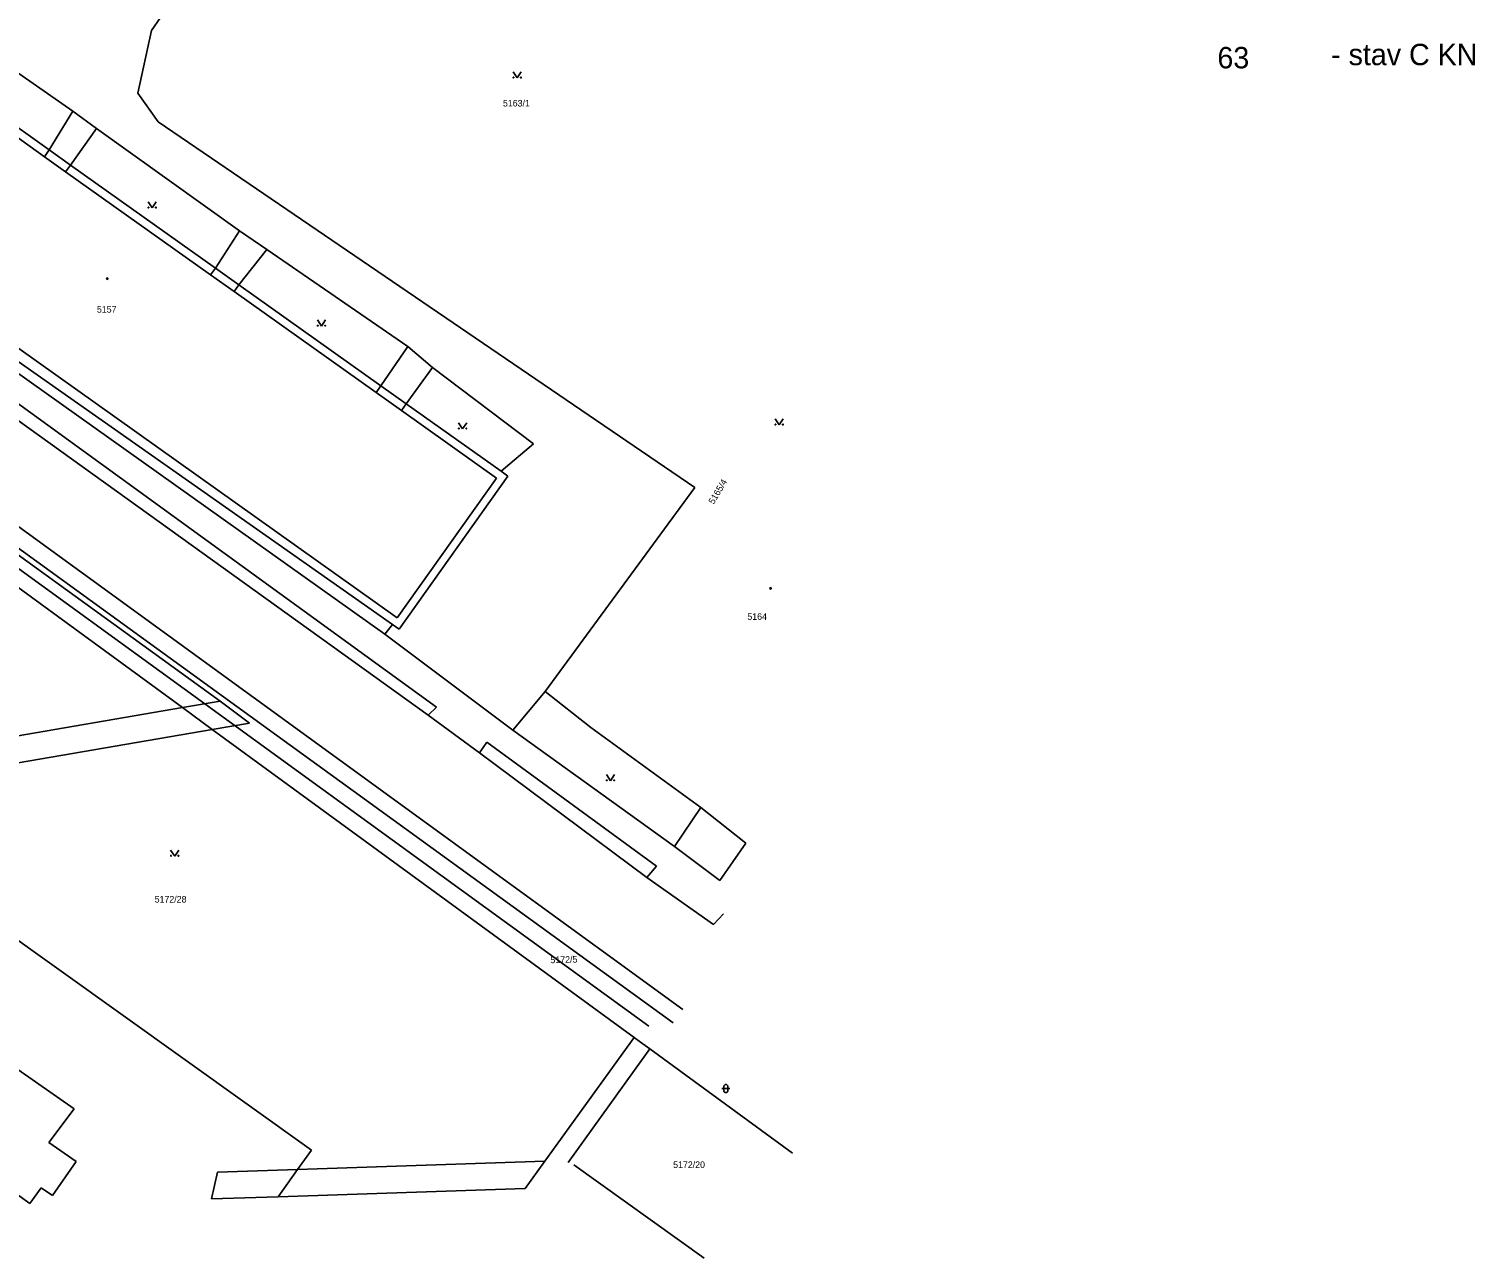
# Model space of a CAD drawing. Extents: x -400488 to -400124, y -1251493 to -1251223.
# Drawn here: x -400248.8 to -400143.3, y -1251492.2 to -1251402.6 of the extents above; entities that cross this region are included whole.
import ezdxf

# ---------------------------------------------------------------- set-up
doc = ezdxf.new("R2010")
doc.units = 0
doc.layers.add('Level 3', color=7, linetype='Continuous')
doc.layers.add('Level 63', color=7, linetype='Continuous')

msp = doc.modelspace()

# ---------------------------------------------------------------- linework, layer by layer
at = {"layer": 'Level 63'}
for p, q in [((-400239.81, -1251402.68), (-400225.97, -1251382.68)), ((-400287.14, -1251402.66), (-400219.04, -1251452.02)), ((-400240.81, -1251407.26), (-400239.81, -1251402.68)), ((-400287.72, -1251403.73), (-400219.65, -1251452.6)), ((-400252.27, -1251403.91), (-400245.56, -1251408.56)), ((-400213.46, -1251405.7), (-400213.16, -1251406.15)), ((-400213.16, -1251406.15), (-400212.86, -1251405.7)), ((-400239.33, -1251409.36), (-400240.81, -1251407.26)), ((-400251.75, -1251408.21), (-400247.28, -1251411.4)), ((-400247.28, -1251411.4), (-400251.75, -1251408.21)), ((-400251.61, -1251409.05), (-400247.63, -1251411.89)), ((-400247.28, -1251411.4), (-400245.56, -1251408.56)), ((-400245.56, -1251408.56), (-400243.84, -1251409.84)), ((-400200.2, -1251436), (-400239.33, -1251409.36)), ((-400245.73, -1251412.5), (-400243.84, -1251409.84)), ((-400243.84, -1251409.84), (-400233.41, -1251417.29)), ((-400247.28, -1251411.4), (-400247.63, -1251411.89)), ((-400247.28, -1251411.4), (-400245.73, -1251412.5)), ((-400245.73, -1251412.5), (-400247.28, -1251411.4)), ((-400287.04, -1251411.61), (-400201.09, -1251474.06)), ((-400247.63, -1251411.89), (-400246.08, -1251412.99)), ((-400245.73, -1251412.5), (-400246.08, -1251412.99)), ((-400245.73, -1251412.5), (-400235.16, -1251420.02)), ((-400235.16, -1251420.02), (-400245.73, -1251412.5)), ((-400286.78, -1251413.41), (-400201.79, -1251475.05)), ((-400246.08, -1251412.99), (-400235.51, -1251420.51)), ((-400203.57, -1251475.28), (-400286.46, -1251415.13)), ((-400240.07, -1251415.18), (-400239.77, -1251415.63)), ((-400239.77, -1251415.63), (-400239.47, -1251415.18)), ((-400235.16, -1251420.02), (-400233.41, -1251417.29)), ((-400233.41, -1251417.29), (-400231.41, -1251418.66)), ((-400233.45, -1251421.23), (-400231.41, -1251418.66)), ((-400231.41, -1251418.66), (-400221.14, -1251425.72)), ((-400258.53, -1251419.46), (-400221.9, -1251445.5)), ((-400258.92, -1251421.03), (-400222.82, -1251446.71)), ((-400222.82, -1251446.71), (-400258.92, -1251421.03)), ((-400222.25, -1251445.99), (-400258.55, -1251420.52)), ((-400258.55, -1251420.52), (-400222.25, -1251445.99)), ((-400235.51, -1251420.51), (-400235.16, -1251420.02)), ((-400233.8, -1251421.72), (-400235.51, -1251420.51)), ((-400235.16, -1251420.02), (-400233.45, -1251421.23)), ((-400233.45, -1251421.23), (-400235.16, -1251420.02)), ((-400233.45, -1251421.23), (-400233.8, -1251421.72)), ((-400223.45, -1251429.08), (-400233.8, -1251421.72)), ((-400233.45, -1251421.23), (-400223.1, -1251428.59)), ((-400223.1, -1251428.59), (-400233.45, -1251421.23)), ((-400227.73, -1251423.79), (-400227.43, -1251424.24)), ((-400227.43, -1251424.24), (-400227.13, -1251423.79)), ((-400223.1, -1251428.59), (-400221.14, -1251425.72)), ((-400221.14, -1251425.72), (-400219.33, -1251427.27)), ((-400221.25, -1251429.91), (-400219.33, -1251427.27)), ((-400219.33, -1251427.27), (-400211.96, -1251432.82)), ((-400223.1, -1251428.59), (-400223.45, -1251429.08)), ((-400221.59, -1251430.4), (-400223.45, -1251429.08)), ((-400223.1, -1251428.59), (-400221.25, -1251429.91)), ((-400221.25, -1251429.91), (-400223.1, -1251428.59)), ((-400221.25, -1251429.91), (-400221.59, -1251430.4)), ((-400214.68, -1251435.32), (-400221.59, -1251430.4)), ((-400221.25, -1251429.91), (-400214.33, -1251434.83)), ((-400214.33, -1251434.83), (-400221.25, -1251429.91)), ((-400217.44, -1251431.29), (-400217.14, -1251431.74)), ((-400217.14, -1251431.74), (-400216.84, -1251431.29)), ((-400194.36, -1251431), (-400194.06, -1251431.45)), ((-400194.06, -1251431.45), (-400193.76, -1251431)), ((-400211.96, -1251432.82), (-400214.33, -1251434.83)), ((-400221.9, -1251445.5), (-400214.68, -1251435.32)), ((-400213.85, -1251435.18), (-400221.76, -1251446.33)), ((-400221.76, -1251446.33), (-400213.85, -1251435.18)), ((-400214.33, -1251434.83), (-400213.85, -1251435.18)), ((-400213.85, -1251435.18), (-400214.33, -1251434.83)), ((-400211.13, -1251450.88), (-400200.2, -1251436)), ((-400200.2, -1251436), (-400211.13, -1251450.88)), ((-400234.81, -1251451.59), (-400250.32, -1251440.37)), ((-400250.32, -1251440.37), (-400234.81, -1251451.59)), ((-400237.56, -1251452.06), (-400251.44, -1251441.92)), ((-400251.44, -1251441.92), (-400237.56, -1251452.06)), ((-400222.25, -1251445.99), (-400222.82, -1251446.71)), ((-400221.76, -1251446.33), (-400222.25, -1251445.99)), ((-400222.25, -1251445.99), (-400221.76, -1251446.33)), ((-400222.82, -1251446.71), (-400213.47, -1251453.7)), ((-400213.47, -1251453.7), (-400222.82, -1251446.71)), ((-400237.56, -1251452.06), (-400234.81, -1251451.59)), ((-400232.67, -1251453.18), (-400234.81, -1251451.59)), ((-400234.81, -1251451.59), (-400232.67, -1251453.18)), ((-400213.47, -1251453.7), (-400211.13, -1251450.88)), ((-400207.8, -1251453.51), (-400211.13, -1251450.88)), ((-400211.13, -1251450.88), (-400207.8, -1251453.51)), ((-400237.56, -1251452.06), (-400261.97, -1251456.23)), ((-400235.39, -1251453.65), (-400237.56, -1251452.06)), ((-400237.56, -1251452.06), (-400235.39, -1251453.65)), ((-400219.04, -1251452.02), (-400219.65, -1251452.6)), ((-400219.65, -1251452.6), (-400215.92, -1251455.35)), ((-400235.39, -1251453.65), (-400263.65, -1251458.51)), ((-400232.67, -1251453.18), (-400235.39, -1251453.65)), ((-400204.63, -1251476.12), (-400235.39, -1251453.65)), ((-400235.39, -1251453.65), (-400204.63, -1251476.12)), ((-400213.47, -1251453.7), (-400201.68, -1251462.19)), ((-400201.68, -1251462.19), (-400213.47, -1251453.7)), ((-400199.78, -1251459.35), (-400207.8, -1251453.51)), ((-400207.8, -1251453.51), (-400199.78, -1251459.35)), ((-400215.92, -1251455.35), (-400215.38, -1251454.58)), ((-400215.38, -1251454.58), (-400203, -1251463.62)), ((-400215.92, -1251455.35), (-400203.71, -1251464.44)), ((-400206.66, -1251456.94), (-400206.36, -1251457.39)), ((-400206.36, -1251457.39), (-400206.06, -1251456.94)), ((-400228.16, -1251484.33), (-400263.87, -1251458.81)), ((-400263.87, -1251458.81), (-400228.16, -1251484.33)), ((-400199.78, -1251459.35), (-400201.68, -1251462.19)), ((-400196.49, -1251461.94), (-400199.78, -1251459.35)), ((-400199.78, -1251459.35), (-400196.49, -1251461.94)), ((-400198.38, -1251464.66), (-400196.49, -1251461.94)), ((-400238.43, -1251462.44), (-400238.13, -1251462.89)), ((-400238.13, -1251462.89), (-400237.83, -1251462.44)), ((-400201.68, -1251462.19), (-400198.38, -1251464.66)), ((-400198.38, -1251464.66), (-400201.68, -1251462.19)), ((-400203, -1251463.62), (-400203.71, -1251464.44)), ((-400203.71, -1251464.44), (-400198.86, -1251467.88)), ((-400198.13, -1251467.09), (-400198.86, -1251467.88)), ((-400253.68, -1251475.56), (-400245.47, -1251481.31)), ((-400245.47, -1251481.31), (-400253.68, -1251475.56)), ((-400211.15, -1251485.13), (-400204.63, -1251476.12)), ((-400204.63, -1251476.12), (-400211.15, -1251485.13)), ((-400204.16, -1251476.46), (-400204.63, -1251476.12)), ((-400204.63, -1251476.12), (-400204.16, -1251476.46)), ((-400203.5, -1251476.94), (-400204.16, -1251476.46)), ((-400204.16, -1251476.46), (-400203.5, -1251476.94)), ((-400209.44, -1251485.21), (-400203.5, -1251476.94)), ((-400193.09, -1251484.53), (-400203.5, -1251476.94)), ((-400203.5, -1251476.94), (-400193.09, -1251484.53)), ((-400198.25, -1251479.83), (-400197.65, -1251479.83)), ((-400198.1, -1251479.68), (-400198.1, -1251479.98)), ((-400197.8, -1251479.68), (-400197.8, -1251479.98)), ((-400248.7, -1251488.21), (-400257.96, -1251481.59)), ((-400257.96, -1251481.59), (-400248.7, -1251488.21)), ((-400245.47, -1251481.31), (-400247.31, -1251483.77)), ((-400247.31, -1251483.77), (-400245.47, -1251481.31)), ((-400247.31, -1251483.77), (-400245.32, -1251485.14)), ((-400245.32, -1251485.14), (-400247.31, -1251483.77)), ((-400245.32, -1251485.14), (-400247.03, -1251487.63)), ((-400247.03, -1251487.63), (-400245.32, -1251485.14)), ((-400229.17, -1251485.73), (-400228.16, -1251484.33)), ((-400228.16, -1251484.33), (-400229.17, -1251485.73)), ((-400229.17, -1251485.73), (-400211.15, -1251485.13)), ((-400212.58, -1251487.11), (-400211.15, -1251485.13)), ((-400211.15, -1251485.13), (-400212.58, -1251487.11)), ((-400235, -1251485.93), (-400235.44, -1251487.88)), ((-400229.17, -1251485.73), (-400235, -1251485.93)), ((-400230.59, -1251487.72), (-400229.17, -1251485.73)), ((-400229.17, -1251485.73), (-400230.59, -1251487.72)), ((-400199.53, -1251492.19), (-400209.02, -1251485.39)), ((-400209.02, -1251485.39), (-400199.53, -1251492.19)), ((-400247.86, -1251487.06), (-400248.7, -1251488.21)), ((-400248.7, -1251488.21), (-400247.86, -1251487.06)), ((-400247.03, -1251487.63), (-400247.86, -1251487.06)), ((-400247.86, -1251487.06), (-400247.03, -1251487.63)), ((-400212.58, -1251487.11), (-400230.59, -1251487.72)), ((-400235.44, -1251487.88), (-400230.59, -1251487.72))]:
    msp.add_line(p, q, dxfattribs=at)
for centre, radius in [((-400213.43, -1251406.12), 0.03), ((-400212.89, -1251406.12), 0.03), ((-400240.04, -1251415.6), 0.03), ((-400239.5, -1251415.6), 0.03), ((-400243.05, -1251420.78), 0.054), ((-400227.7, -1251424.21), 0.03), ((-400227.16, -1251424.21), 0.03), ((-400194.33, -1251431.42), 0.03), ((-400193.79, -1251431.42), 0.03), ((-400217.41, -1251431.71), 0.03), ((-400216.87, -1251431.71), 0.03), ((-400194.69, -1251443.36), 0.054), ((-400206.63, -1251457.36), 0.03), ((-400206.09, -1251457.36), 0.03), ((-400238.4, -1251462.86), 0.03), ((-400237.86, -1251462.86), 0.03)]:
    msp.add_circle(centre, radius, dxfattribs=at)
for centre, start, end in [((-400197.95, -1251479.68), 0, 180), ((-400197.95, -1251479.98), 180, 0)]:
    msp.add_arc(centre, 0.15, start, end, dxfattribs=at)

# ---------------------------------------------------------------- texts
at = {"layer": 'Level 3'}
for s, p in [('63', (-400162.11, -1251405.45)), (' - stav C KN', (-400154.4, -1251405.22))]:
    msp.add_text(s, height=1.56, dxfattribs=at).set_placement(p)
at = {"layer": 'Level 63'}
for s, p in [('5163/1', (-400214.2, -1251408.23)), ('5157', (-400243.8, -1251423.26)), ('5164', (-400196.38, -1251445.66)), ('5172/28', (-400239.59, -1251466.27)), ('5172/20', (-400201.79, -1251485.62))]:
    msp.add_text(s, height=0.48, dxfattribs=at).set_placement(p)
for s, rotation, p in [('5165/4', 59.4, (-400198.83, -1251437.27)), ('5172/5', 1.28, (-400210.73, -1251470.69))]:
    msp.add_text(s, height=0.48, rotation=rotation, dxfattribs=at).set_placement(p)

doc.saveas('drawing.dxf')
